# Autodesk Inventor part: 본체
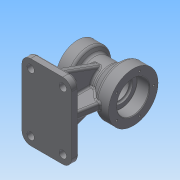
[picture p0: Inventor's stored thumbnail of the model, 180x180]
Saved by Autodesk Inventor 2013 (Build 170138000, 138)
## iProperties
Created: 2015-08
Part Number: 본체
Material: 일반
Document SubType Name: Modeling
Designer: Administrator
Density: 1 g/cm^3
Author: Administrator
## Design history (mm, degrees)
sketch "스케치1"
  geometry: L1 (0, 0)-(90, 0); L2 (0, 0)-(0, 35); L3 (0, 35)-(20, 35); L4 (20, 35)-(25.196, 26); L5 (25.196, 26)-(53.315, 26); L6 (53.315, 26)-(70, 40); L7 (70, 40)-(90, 40); L8 (90, 40)-(90, 0)
  constraints: 16 end point, 3 parallel, 2 perpendicular, 1 horizontal
  dimensions: "d0" = 90 distance of L1.start L1.end; "d1" = 70 diameter of L3 L1; "d2" = 52 diameter of L5 L1; "d3" = 80 diameter of L7 L1; "d4" = 40 deg angle of L5 L6; "d5" = 60 deg angle of L4 L5; "d6" = 20 distance of L2.end L3.end; "d7" = 20 distance of L6.end L7.end
revolve "회전1" sketch "스케치1" stored, may be unused: angle "d8" = 90 deg
sketch "스케치2"
  geometry: L1 (-61, -78)-(61, -78); L2 (61, -78)-(61, -90); L3 (61, -90)-(-61, -90); L4 (-61, -90)-(-61, -78); C1 r 35 at (0, 0) reference; 1 further point
  constraints: 8 end point, 2 parallel, 1 horizontal, 1 midpoint, 1 perpendicular, 1 vertical alignment
  dimensions: "d9" = 122 distance of L2.end L3.end; "d10" = 12 distance of L1.end L2.end; "d11" = 90 distance from line of C1.centre L3
extrude "돌출1" join sketch "스케치2" distance "d12" = 80; taper "d13" = 0 deg
node "작업 평면1"
sketch "스케치3"
  geometry: L1 (61, -78)-(61, -90) reference; L2 (61, -90)-(-61, -90) reference; L3 (-61, -90)-(-61, -78) reference; L4 (-61, -78)-(61, -78) reference; L5 (-25.091, -6.815)-(-51, -78); L6 (25.091, -6.815)-(51, -78); A1 r 26 centre (0, 0) between (-25.091, -6.815) and (25.091, -6.815) reference; 1 further point
  constraints: 4 end point, 2 point on circle, 2 point on line, 1 equal length
  dimensions: "d14" = 70 deg angle of L4 L6; "d15" = 70 deg angle of L4 L5; "d16" = 10 distance from line of L1 L6.end
extrude "돌출2" join sketch "스케치3" stored distance "d17" = 12; taper "d18" = 0 deg
sketch "스케치4"
  geometry: L1 (0, -35)-(0, 35) reference; L2 (0, 35)-(20, 35) reference; L3 (20, 35)-(25.196, 26) reference; L4 (25.196, 26)-(53.315, 26) reference; L5 (53.315, 26)-(70, 40) reference; L6 (70, 40)-(90, 40) reference; L7 (90, 40)-(90, -40) reference; L8 (90, -40)-(70, -40) reference; L9 (70, -40)-(53.315, -26) reference; L10 (53.315, -26)-(46, -26) reference; L11 (46, -26)-(46, -78) reference; L12 (46, -78)-(80, -78) reference; L13 (80, -78)-(80, -90) reference; L14 (80, -90)-(0, -90) reference; L15 (0, -90)-(0, -78) reference; L16 (0, -78)-(34, -78) reference; L17 (34, -78)-(34, -26) reference; L18 (34, -26)-(25.196, -26) reference; L19 (25.196, -26)-(20, -35) reference; L20 (20, -35)-(0, -35) reference; L21 (10, -35)-(10, -78); L22 (76.7, -40)-(70, -78); 1 further point
  constraints: 4 end point, 3 point on line, 1 midpoint, 1 perpendicular
  dimensions: "d19" = 10 distance from line of L15 L21.end; "d20" = 10 distance from line of L13 L22.end; "d21" = 80 deg angle of L12 L22
  node "절단 모서리 투영2"
feature "리브1" dims "d22" = 1, "d23" = 12, "d24" = 0, "d25" = 0, "d26" = 1, "d27" = 1
feature "리브2" dims "d28" = 1, "d29" = 12, "d30" = 0, "d31" = 0, "d32" = 1, "d33" = 1
fillet "모깎기1" dims "d34" = 14
hole "구멍1" diameter "d37" = 38; stored, may be unused: countersink angle "d41" = 90 deg, drill point angle "d43" = 0 deg; dims "d35" = 10, "d36" = 10, "d38" = 6, "d39" = 52, "d40" = 20, "d42" = 23
hole "구멍2" diameter "d46" = 32; stored, may be unused: countersink angle "d50" = 90 deg, drill point angle "d52" = 0 deg; dims "d44" = 10, "d45" = 10, "d47" = 6, "d48" = 40, "d49" = 17, "d51" = 23
fillet "모깎기2" dims "d53" = 0.3
fillet "모깎기3" dims "d54" = 3
chamfer "모따기1" distance "d55" = 1; stored, may be unused: second distance "d56" = 2, angle "d57" = 45 deg
sketch "스케치5"
  geometry: C1 r 40 at (0, 0) reference; 1 further point
  constraints: 1 vertical alignment
  dimensions: "d58" = 33 distance of point (0, 33) C1.centre
hole "구멍3" sketch "스케치5" at (0, 33) diameter "d59" = 3.242; stored, may be unused: countersink angle "d63" = 90 deg, drill point angle "d65" = 118 deg; dims "d60" = 10, "d61" = 40, "d62" = 17, "d64" = 13
sketch "스케치6"
  geometry: C1 r 35 at (0, 0) reference; 1 further point
  constraints: 1 vertical alignment
  dimensions: "d69" = 27 distance of point (0, 27) C1.centre
hole "구멍4" sketch "스케치6" at (0, 27) diameter "d70" = 3.242; stored, may be unused: countersink angle "d74" = 90 deg, drill point angle "d76" = 118 deg; dims "d71" = 10, "d72" = 40, "d73" = 17, "d75" = 13
sketch "스케치7"
  geometry: C1 r 6 at (14, 94); C2 r 6 at (66, 94); C3 r 6 at (14, 0); C4 r 6 at (66, 0); A1 r 14 centre (14, 94) between (14, 108) and (0, 94) reference; A2 r 14 centre (14, 0) between (0, 0) and (14, -14) reference; A3 r 14 centre (66, 0) between (66, -14) and (80, 0) reference; A4 r 14 centre (66, 94) between (80, 94) and (66, 108) reference; 1 further point
  constraints: 4 centre point, 4 coincident
  dimensions: "d80" = 12 diameter of C1; "d81" = 12 diameter of C2; "d82" = 12 diameter of C3; "d83" = 12 diameter of C4
extrude "돌출3" cut sketch "스케치7" stored distance "d84" = 12; taper "d85" = 0 deg
sketch "스케치8"
  geometry: L1 (47, -78)-(61, -78) reference; L2 (18, -54)-(18, -60); L3 (30, -54)-(30, -60); A1 r 26 centre (0, 0) between (6, -25.298) and (25.091, -6.815) reference; A2 r 6 centre (24, -60) between (18, -60) and (30, -60); A3 r 6 centre (24, -54) between (30, -54) and (18, -54)
  constraints: 4 end point, 4 point on circle, 4 tangent, 2 centre point, 1 vertical alignment
  dimensions: "d86" = 12 diameter of A2; "d87" = 12 diameter of A3; "d89" = 24 horizontal distance of A3.centre A1.centre; "d90" = 18 distance from line of A2.centre L1; "d101" = 6 distance of A2.centre A3.centre
extrude "돌출4" cut sketch "스케치8" stored distance "d91" = 12; taper "d92" = 0 deg
fillet "모깎기4" dims "d93" = 5
fillet "모깎기5" dims "d94" = 3
fillet "모깎기6" dims "d95" = 3
fillet "모깎기7" dims "d96" = 3
sketch "스케치9"
  geometry: L1 (-10, -3)-(1, -3) reference; L2 (-3, 37.119)-(-3, 0) reference; 2 further points
  constraints: 1 other
  dimensions: "d97" = 24 distance from line of L1 point (13, 21); "d98" = 16 distance from line of L2 point (13, 21)
feature "엠보싱1" sketch "스케치9" dims "d0" = 90, "d1" = 70, "d2" = 52, "d3" = 80, "d4" = 40 deg, "d5" = 60 deg, "d6" = 20, "d7" = 20, "d99" = 0.5, "d100" = 0
node "솔리드1"
pattern_circular "원형 패턴1" dims angle "d67" = 360 deg
pattern_circular "원형 패턴2" dims angle "d78" = 360 deg
mirror "대칭1"
node "절단 모서리 투영1"
